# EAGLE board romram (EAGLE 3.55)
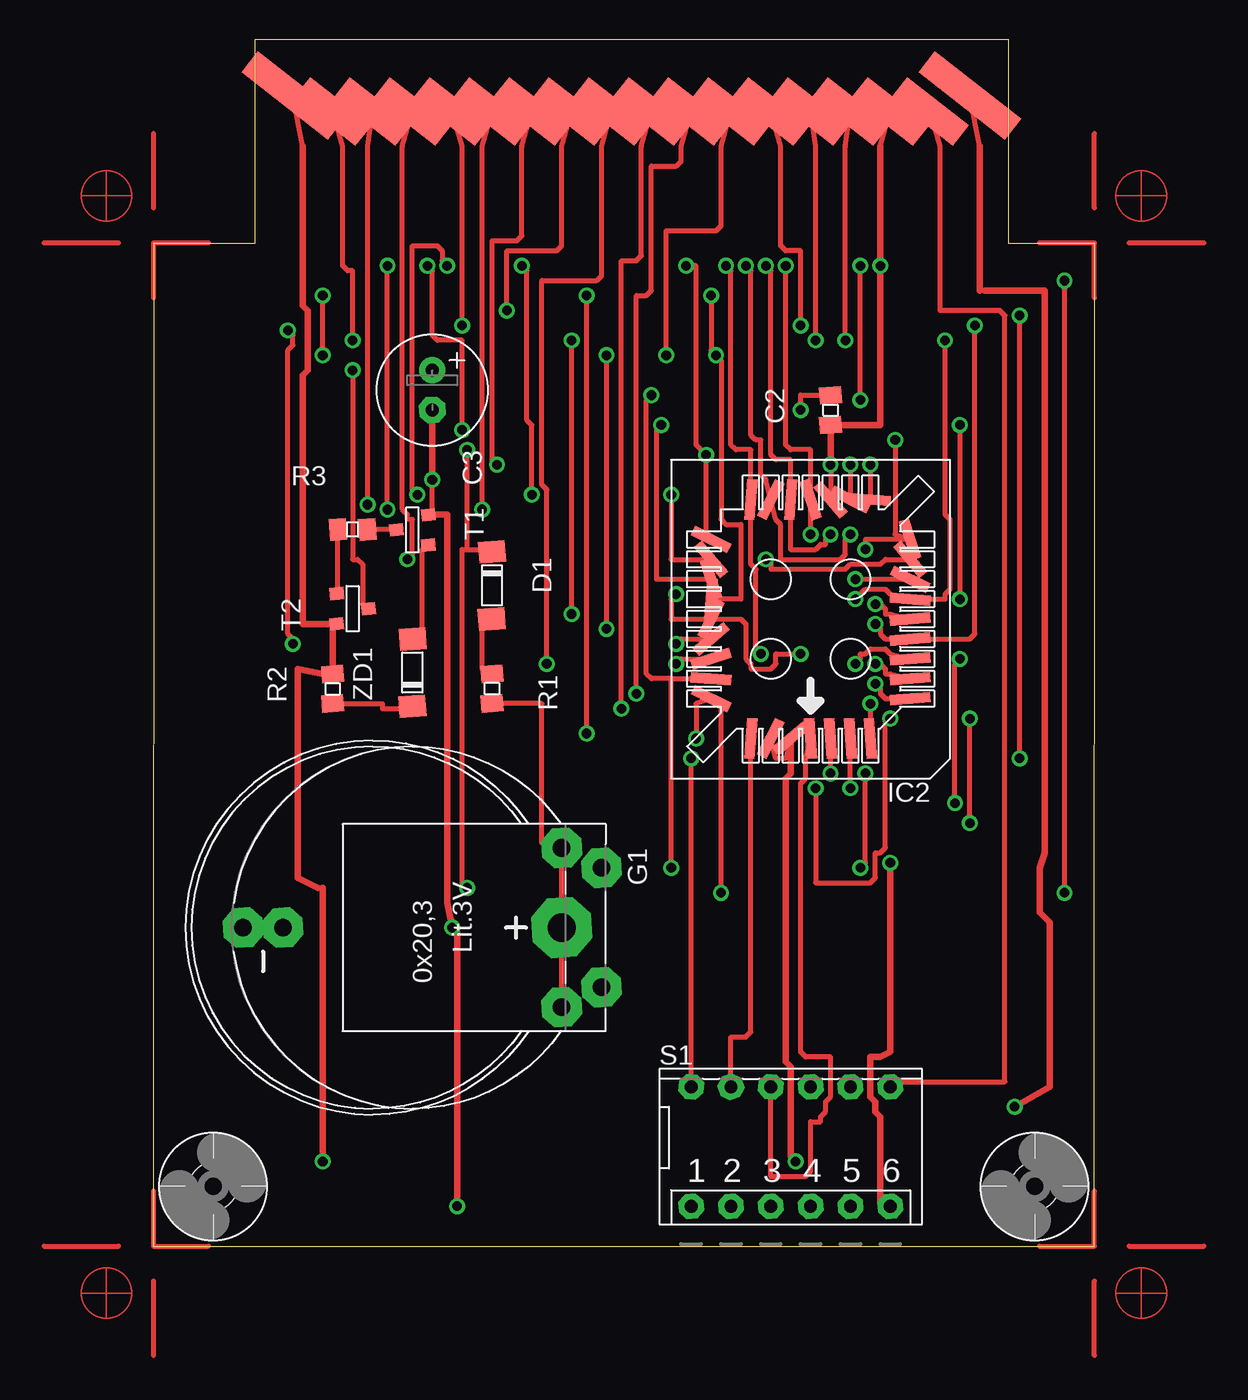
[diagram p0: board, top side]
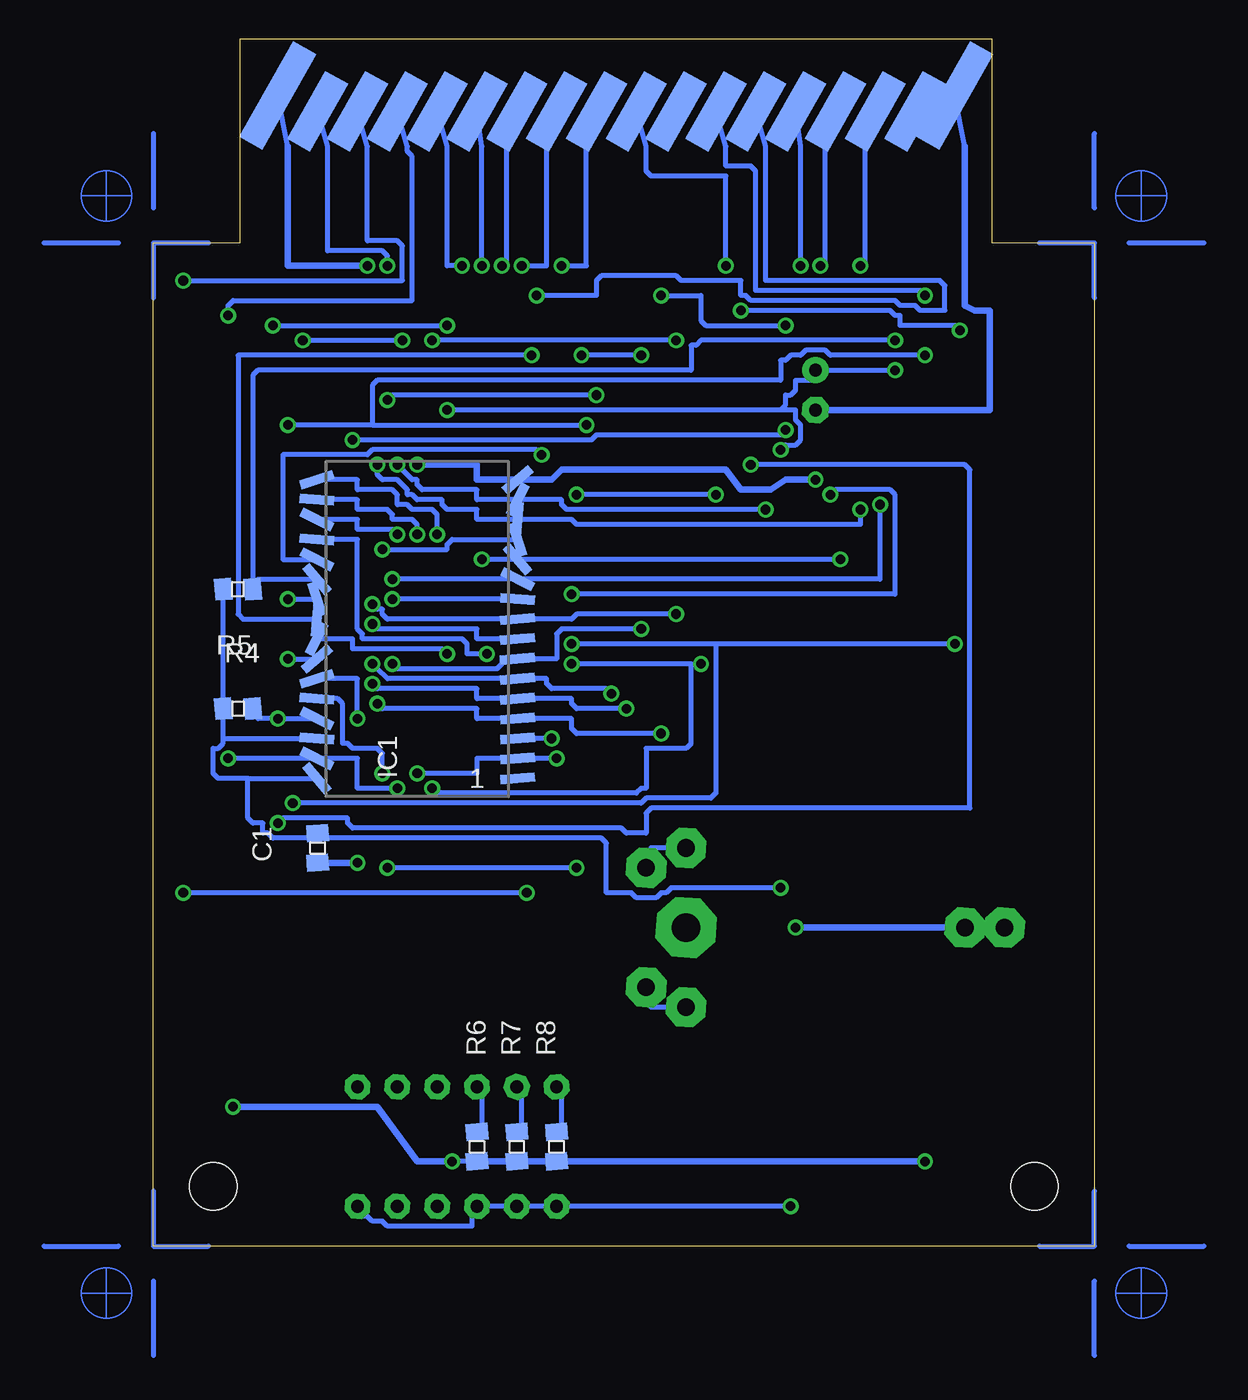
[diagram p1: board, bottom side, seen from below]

Size 60.03 x 77 mm. Coordinates in mm from the lower left corner, seen from the top.
Outline: 60.03,64.01 60.02,0 0,0 0.02,64.01
Outline: 0.01,64 6.51,64 6.51,77 54.51,77 54.51,64 60.01,64
Copper layers used: Top, Bottom
tRestrict: area 10.2,74.9 to 50.8,77.5
bRestrict: area 10.2,74.9 to 50.8,77.5
vRestrict: area 7.6,63.5 to 53.4,69.8

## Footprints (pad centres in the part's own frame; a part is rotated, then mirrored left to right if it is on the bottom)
05 = smd 1.092 x 1.397 rotated 4.4:  0.94,0 | smd 1.092 x 1.397 rotated 4.3:  -0.94,0
2,5-7 = drill 0.813 pad 1.676 round:  -1.27,0 | drill 0.813 pad 1.676 octagon:  1.27,0
KCON = smd 1.676 x 4.978 rotated 52: 0 20.32,2.54; 1 17.78,2.54; 2 15.24,2.54; 3 12.7,2.54; 4 10.16,2.54; 5 7.62,2.54; 6 5.08,2.54; 7 2.54,2.54;  22.86,2.54;  25.4,2.54;  27.94,2.54;  30.48,2.54;  33.02,2.54;  35.56,2.54;  38.1,2.54;  40.64,2.54 | smd 1.676 x 4.978 rotated 29.5 bottom: 0 20.32,2.54; 1 17.78,2.54; 2 15.24,2.54; 3 12.7,2.54; 4 10.16,2.54; 5 7.62,2.54; 6 5.08,2.54; 7 2.54,2.54;  22.86,2.54;  25.4,2.54;  27.94,2.54;  30.48,2.54;  33.02,2.54;  35.56,2.54;  38.1,2.54;  40.64,2.54 | smd 1.676 x 6.985 rotated 52: 8 0,3.556;  43.18,3.556 | smd 1.676 x 6.985 rotated 29.5 bottom: 8 0,3.556;  43.18,3.556
D-80 = smd 1.397 x 1.702 rotated 4.4:  -2.388,0 | smd 1.397 x 1.702 rotated 4.3:  1.905,-0.025
430UNI = drill 1.118 pad 2.54 octagon:  -3.81,14.605;  3.81,14.605;  0,-5.715;  5.08,12.065;  -5.08,12.065;  0,-8.255 | drill 1.803 pad 3.81 octagon:  0,12.065
P32 = smd 0.6 x 2.2 rotated 4.3:  -9.525,-6.4;  1.905,-6.4 | smd 0.6 x 2.2 rotated 4.4:  -8.255,-6.4;  5.715,6.4 | smd 0.6 x 2.2 rotated 4.5:  -6.985,-6.4;  -6.985,6.4 | smd 0.6 x 2.2 rotated 4.6:  -5.715,-6.4 | smd 0.6 x 2.2 rotated 4.7:  -4.445,-6.4;  -3.175,-6.4 | smd 0.6 x 2.2 rotated 4.8:  -1.905,-6.4 | smd 0.6 x 2.2 rotated 4.9:  -0.635,-6.4 | smd 0.6 x 2.2 rotated 5:  0.635,-6.4 | smd 0.6 x 2.2 rotated 26.8:  3.175,-6.4 | smd 0.6 x 2.2 rotated 49.3:  4.445,-6.4 | smd 0.6 x 2.2 rotated 71.8:  5.715,-6.4 | smd 0.6 x 2.2 rotated 94.3:  6.985,-6.4 | smd 0.6 x 2.2 rotated 116.8:  8.255,-6.4 | smd 0.6 x 2.2 rotated 139.3:  9.525,-6.4 | smd 0.6 x 2.2 rotated 161.8:  9.525,6.4 | smd 0.6 x 2.2 rotated 184.3:  8.255,6.4 | smd 0.6 x 2.2 rotated 206.8:  6.985,6.4 | smd 0.6 x 2.2 rotated 26.9:  4.445,6.4 | smd 0.6 x 2.2 rotated 49.4:  3.175,6.4 | smd 0.6 x 2.2 rotated 71.9:  1.905,6.4 | smd 0.6 x 2.2 rotated 94.4:  0.635,6.4 | smd 0.6 x 2.2 rotated 116.9:  -0.635,6.4 | smd 0.6 x 2.2 rotated 139.4:  -1.905,6.4 | smd 0.6 x 2.2 rotated 161.9:  -3.175,6.4 | smd 0.6 x 2.2 rotated 184.4:  -4.445,6.4 | smd 0.6 x 2.2 rotated 206.9:  -5.715,6.4 | smd 0.6 x 2.2 rotated 27:  -8.255,6.4 | smd 0.6 x 2.2 rotated 49.5:  -9.525,6.4
CC32SM = smd 2.591 x 0.66 rotated 161.9:  6.35,1.905 | smd 2.591 x 0.66 rotated 184.4:  6.35,3.175 | smd 0.66 x 2.591 rotated 4.3:  0,6.985 | smd 0.66 x 2.591 rotated 4.4:  -1.27,6.985;  3.81,-8.255 | smd 0.66 x 2.591 rotated 4.5:  -2.54,6.985;  3.81,6.985 | smd 2.591 x 0.66 rotated 139.4:  6.35,0.635 | smd 0.66 x 2.591 rotated 4.6:  -3.81,6.985 | smd 0.66 x 2.591 rotated 161.8:  0,-8.255 | smd 0.66 x 2.591 rotated 139.3:  -1.27,-8.255 | smd 0.66 x 2.591 rotated 116.8:  -2.54,-8.255 | smd 0.66 x 2.591 rotated 94.3:  -3.81,-8.255 | smd 2.591 x 0.66 rotated 71.8:  -6.35,-5.715 | smd 0.66 x 2.591 rotated 184.3:  1.27,-8.255 | smd 2.591 x 0.66 rotated 49.3:  -6.35,-4.445 | smd 2.591 x 0.66 rotated 4.7:  -6.35,4.445;  -6.35,3.175 | smd 2.591 x 0.66 rotated 4.8:  -6.35,1.905 | smd 2.591 x 0.66 rotated 4.9:  -6.35,0.635 | smd 2.591 x 0.66 rotated 5:  -6.35,-0.635 | smd 2.591 x 0.66 rotated 4.3:  -6.35,-1.905 | smd 2.591 x 0.66 rotated 26.8:  -6.35,-3.175 | smd 2.591 x 0.66 rotated 116.9:  6.35,-0.635 | smd 2.591 x 0.66 rotated 94.4:  6.35,-1.905 | smd 2.591 x 0.66 rotated 71.9:  6.35,-3.175 | smd 2.591 x 0.66 rotated 49.4:  6.35,-4.445 | smd 2.591 x 0.66 rotated 26.9:  6.35,-5.715 | smd 0.66 x 2.591 rotated 206.8:  2.54,-8.255 | smd 2.591 x 0.66 rotated 206.9:  6.35,4.445 | smd 0.66 x 2.591 rotated 27:  2.54,6.985 | smd 0.66 x 2.591 rotated 49.5:  1.27,6.985
-06 = drill 0.813 pad 1.6 octagon:  -6.35,-3.81;  -3.81,-3.81;  6.35,3.81;  3.81,3.81;  -1.27,-3.81;  1.27,-3.81;  6.35,-3.81;  3.81,-3.81;  1.27,3.81;  -1.27,3.81;  -3.81,3.81;  -6.35,3.81
T23 = smd 0.787 x 0.889 rotated 5.8:  0.991,1.016 | smd 0.787 x 0.889 rotated 6.1:  -0.94,1.016 | smd 0.787 x 0.889 rotated 5.9:  0.025,-1.016
3,0 = hole 3.023: 0,0

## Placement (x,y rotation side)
C1  100nF  [05]  49.54,25.4 90 bottom
C2  100nF  [05]  43.19,53.34 90 top
C3  47uF  [2,5-7]  17.79,54.61 270 top
CON1  TEKCON  [KCON]  8.9,69.85 0 top
D1  1N4148  [D-80]  21.6,41.91 270 top
G1  B2430UNI  [430UNI]  13.98,20.32 270 top
IC1  628128S  [P32]  43.19,39.37 90 bottom
IC2  29F040JCS  [CC32SM]  41.92,39.37 180 top
R1  200  [05]  21.6,35.56 270 top
R2  10k  [05]  11.44,35.56 90 top
R3  510  [05]  12.71,45.72 180 top
R4  1k  [05]  54.62,34.29 0 bottom
R5  1k  [05]  54.62,41.91 180 bottom
R6  10k  [05]  39.38,6.35 90 bottom
R7  10k  [05]  36.84,6.35 90 bottom
R8  10k  [05]  34.3,6.35 90 bottom
S1  DP06  [-06]  40.65,6.35 0 top
T1  BC848  [T23]  16.52,45.72 270 top
T2  BC858  [T23]  12.71,40.64 90 top
U$1  [H]  0.01,64 180 top
U$2  [H]  60.01,64 90 top
U$3  [H]  0.01,0 270 top
U$4  [H]  60.01,0 0 top
U$5  [IZ]  -2.99,67 0 top
U$6  [IZ]  63.01,67 0 top
U$7  [IZ]  63.01,-3 0 top
U$8  [IZ]  -2.99,-3 0 top
U$9  [3,0]  56.21,3.81 0 top
U$10  [3,0]  3.82,3.81 0 top
ZD1  3.6V  [D-80]  16.52,36.83 90 top

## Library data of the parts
C1 C2 D1 R1-R8 ZD1 = SMD
C3 = cap-pan
CON1 IC2 = Moje1
G1 = BATTERY
IC1 = MEMHITCH
S1 = DILSWTCH
T1 T2 = TRANS-SM
U$1-U$8 = VYKRESY
U$9 U$10 = HOLES

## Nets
+5V: CON1. CON1.8 IC2. R2. R6. R7. R8. T2.
A0: CON1.5 IC1. IC2.
A1: CON1.6 IC1. IC2.
A2: CON1. IC1. IC2.
A3: CON1. IC1. IC2.
A4: CON1. IC1. IC2.
A5: CON1. IC1. IC2.
A6: CON1. IC1. IC2.
A7: CON1. IC1. IC2.
A8: CON1.0 IC1. IC2.
A9: CON1.1 IC1. IC2.
A10: CON1.2 IC1. IC2.
A11: CON1.4 IC1. IC2.
A12: CON1.4 IC1. IC2.
A13: CON1. IC1. IC2.
A14: CON1. IC1. IC2.
A15: CON1. IC1. IC2.
A16: IC1. IC2. R8. S1.
A17: IC2. R7. S1.
A18: IC2. R6. S1.
D0: CON1.5 IC1. IC2.
D1: CON1.6 IC1. IC2.
D2: CON1.3 IC1. IC2.
D3: CON1. IC1. IC2.
D4: CON1. IC1. IC2.
D5: CON1. IC1. IC2.
D6: CON1. IC1. IC2.
D7: CON1. IC1. IC2.
GND: C1. C2. C3. CON1. CON1.8 G1. IC1. IC2. S1. T1.
N$1: CON1.3 IC1. IC2.
N$2: R3. T2.
N$3: G1. R1.
N$4: D1. R1.
N$5: R3. T1.
N$6: R2. ZD1.
N$7: T1. ZD1.
N$9: CON1. S1.
N$10: CON1.0 IC2.
N$11: CON1.7 IC1. R5.
N$22: CON1.2 IC1. R4.
VBAT: C1. C2. C3. D1. IC1. R4. R5. T2.

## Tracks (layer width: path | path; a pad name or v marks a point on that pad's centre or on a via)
+5V  (via drill 0.61 pad 1.02)
  Top 0.305: 11.44,39.37 11.69,39.7 11.44,39.69 | 9.54,70.17 CON1.8 | 39.38,32.38 39.7,31.11 40.33,31.11 40.65,32.38 | v40.97,5.4 40.65,5.71 | 53.03,60.96 52.71,60.96 | 52.71,70.17 52.08,73.41 | 10.8,22.86 10.49,22.86 | 10.8,36.51 11.44,36.5
  Top 0.406: 11.44,36.5 11.44,39.37 | 11.44,39.69 9.54,39.69 9.54,55.56 9.85,55.88 9.85,59.69 9.54,60.01 9.54,70.17 | 40.65,5.71 40.65,11.43 40.33,11.75 40.33,29.84 40.65,30.16 40.65,32.38 | 52.71,60.96 52.71,70.17 | 53.03,60.96 56.84,60.96 56.84,25.08 56.52,24.13 56.52,21.27 57.16,20.64 57.16,10.16 v54.94,8.89 | 10.8,36.51 9.22,36.83 9.22,23.5 10.49,22.86 | v10.8,5.4 10.8,22.86
  Bottom 0.305: 34.93,5.4 R8. 33.66,5.4 | 36.2,5.4 R7. 37.48,5.4 | 38.74,5.4 R6. 40.02,5.4 v40.97,5.4
  Bottom 0.406: 34.93,5.4 36.2,5.4 | 37.48,5.4 38.74,5.4 | v40.97,5.4 43.19,5.4 45.73,8.89 v54.94,8.89 | v10.8,5.4 33.66,5.4
A0  (via drill 0.61 pad 1.02)
  Top 0.305: v39.06,43.81 39.38,43.5 39.38,43.18 44.14,43.18 44.46,43.5 46.36,43.5 46.68,43.81 48.27,43.81 | v16.2,43.81 16.52,44.13 16.52,46.35 16.2,46.35 16.2,46.67 15.88,46.99 15.88,70.17 CON1.5
  Bottom 0.305: v39.06,43.81 36.79,43.81 v16.2,43.81
A1  (via drill 0.61 pad 1.02)
  Top 0.305: v44.78,42.55 48.27,42.55 | v13.66,47.31 13.66,70.17 CON1.6
  Bottom 0.305: v44.78,42.55 36.79,42.55 13.66,42.55 v13.66,47.31
A2  (via drill 0.61 pad 1.02)
  Top 0.305: v44.78,41.27 45.09,41.27 45.09,41.59 45.41,41.91 46.68,41.91 47,41.59 48.27,41.27 50.49,41.27 50.49,41.59 50.81,41.91 50.81,46.35 50.49,46.67 v50.49,57.78 | v44.14,57.78 44.14,70.17 44.46,72.39
  Bottom 0.305: 36.79,41.27 v44.78,41.27 | v50.49,57.78 v44.14,57.78
A3  (via drill 0.61 pad 1.02)
  Top 0.305: v46.05,40.96 46.36,40.96 46.68,40.64 46.68,40.32 47,40.32 48.27,40.01 | v42.24,57.78 42.24,70.17 41.92,72.39 | v26.68,40.32 v26.68,57.78
  Bottom 0.305: v46.05,40.96 45.73,40.64 45.41,40.64 45.41,40.32 45.09,40.01 36.79,40.01 33.35,40.01 33.03,40.32 v26.68,40.32 | v26.68,57.78 v42.24,57.78
A4  (via drill 0.61 pad 1.02)
  Top 0.305: v46.05,39.69 46.36,39.37 46.36,39.05 46.68,38.73 48.27,38.73 52.08,38.73 52.4,39.05 v52.4,58.74 | v41.28,58.74 41.28,63.5 40.33,63.5 40.02,63.82 40.02,70.17 39.38,72.39
  Bottom 0.305: v46.05,39.69 45.73,39.37 39.38,39.37 39.38,38.73 36.79,38.73 | v52.4,58.74 v41.28,58.74
A5  (via drill 0.61 pad 1.02)
  Top 0.305: v44.78,37.15 45.09,37.47 45.09,37.78 45.41,37.78 45.73,38.1 46.68,38.1 47,37.78 48.27,37.47 | v32.71,56.83 32.71,64.77 35.89,64.77 36.2,65.09 36.2,70.17 36.84,72.39 | v28.9,39.37 v28.9,56.83
  Bottom 0.305: v44.78,37.15 44.46,36.83 38.11,36.83 37.79,37.15 37.79,37.47 36.79,37.47 34.3,37.47 34.3,39.05 33.98,39.37 v28.9,39.37 | v28.9,56.83 v32.71,56.83
A6  (via drill 0.61 pad 1.02)
  Top 0.305: v46.05,37.15 46.36,37.15 46.68,36.83 46.68,36.51 47,36.51 48.27,36.2 | v30.81,35.24 30.81,60.64 31.44,60.64 31.76,60.96 31.76,68.9 33.35,68.9 33.66,69.22 33.66,70.17 34.3,72.39
  Bottom 0.305: v46.05,37.15 46.05,36.83 45.73,36.83 45.09,36.2 36.79,36.2 34.93,36.2 34.93,35.88 34.62,35.56 31.12,35.56 v30.81,35.24
A7  (via drill 0.61 pad 1.02)
  Top 0.305: v46.05,35.88 46.36,35.56 46.36,35.24 46.68,34.92 48.27,34.92 | v29.86,34.29 29.86,62.87 30.81,62.87 31.12,63.18 31.12,70.17 31.76,72.39
  Bottom 0.305: v46.05,35.88 45.73,35.56 39.38,35.56 39.38,34.92 36.79,34.92 33.35,34.92 33.35,34.61 33.03,34.29 v29.86,34.29
A8  (via drill 0.61 pad 1.02)
  Top 0.305: v47,33.66 46.68,33.34 46.68,25.4 46.36,25.08 46.05,25.08 46.05,23.5 45.73,23.18 42.24,23.18 v42.24,29.21 | v33.35,37.15 33.66,37.47 35.57,37.47 | v25.09,37.15 25.09,48.26 24.78,48.58 24.78,61.59 28.27,61.59 28.59,61.91 28.59,70.17 CON1.0
  Bottom 0.305: v47,33.66 47,36.2 49.59,36.2 | v42.24,29.21 41.92,28.89 29.22,28.89 28.9,29.21 28.59,29.21 28.59,31.75 26.05,31.75 25.73,32.07 25.73,37.15 | 25.73,37.15 v33.35,37.15 | 25.73,37.15 v25.09,37.15
A9  (via drill 0.61 pad 1.02)
  Top 0.305: v51.45,37.47 51.13,37.15 v51.13,28.26 | v33.35,38.42 33.66,38.73 35.57,38.73 | v22.55,59.69 22.55,63.5 25.73,63.5 26.05,63.82 26.05,70.17 CON1.1 | v8.58,58.42 8.9,58.1 8.9,57.47 8.58,57.15 8.58,39.05 8.9,38.73 v8.9,38.42
  Bottom 0.305: v51.13,28.26 28.9,28.26 28.59,28.57 24.46,28.57 24.14,28.89 24.14,38.42 | 24.14,38.42 v33.35,38.42 | v51.45,37.47 49.59,37.47 | v22.55,59.69 13.03,59.69 12.71,59.37 12.39,59.37 12.39,58.74 8.9,58.74 v8.58,58.42 | v8.9,38.42 24.14,38.42
A10  (via drill 0.61 pad 1.02)
  Top 0.305: v51.45,52.39 v51.45,41.27 | v32.39,52.39 32.08,52.07 32.08,42.55 35.57,42.55 | v10.8,56.83 v10.8,60.64
  Bottom 0.305: 46.05,52.39 v32.39,52.39 | 46.05,52.39 v51.45,52.39 | v51.45,41.27 49.59,41.27 | v10.8,60.64 11.12,60.96 21.6,60.96 21.6,68.58 21.92,68.9 23.51,68.9 23.51,70.17 CON1.2 | v10.8,56.83 16.84,56.83 17.16,57.15 18.43,57.15 18.74,56.83 19.38,56.83 19.7,56.52 20.01,56.52 20.01,55.24 45.73,55.24 46.05,54.93 46.05,52.39
A11  (via drill 0.61 pad 1.02)
  Top 0.305: v41.28,37.78 39.7,37.78 39.7,37.15 39.38,36.83 38.11,36.83 38.11,37.15 37.79,37.47 37.79,39.69 37.48,40.01 35.57,40.01 33.03,40.01 33.03,41.27 v33.35,41.59 | v18.74,62.55 18.43,62.87 18.43,63.5 18.11,63.82 16.52,63.82 16.52,48.26 v16.84,47.94
  Bottom 0.305: v41.28,37.78 41.6,38.1 47.32,38.1 47.32,38.73 49.59,38.73 | v18.74,62.55 18.74,70.17 CON1.4 | v16.84,47.94 16.52,48.26 13.03,48.26 12.71,47.94 12.71,41.59 v33.35,41.59
A12  (via drill 0.61 pad 1.02)
  Top 0.305: v45.73,34.61 45.73,32.38 | v19.7,58.74 19.7,70.17 CON1.4 | v27.63,32.7 v27.63,60.64
  Bottom 0.305: v45.73,34.61 45.41,34.29 39.38,34.29 39.38,33.66 36.79,33.66 33.35,33.66 33.35,33.02 33.03,32.7 v27.63,32.7 | v19.7,58.74 24.78,58.74 25.09,59.05 25.09,60.64 v27.63,60.64
A13  (via drill 0.61 pad 1.02)
  Top 0.305: v45.41,30.16 45.41,24.45 v45.09,24.13 | v33.03,24.13 33.03,36.2 | 33.03,36.2 35.57,36.2 | v45.09,53.98 v45.09,62.55 | v31.76,54.29 31.44,53.98 31.44,36.51 31.76,36.2 33.03,36.2
  Bottom 0.305: v45.41,30.16 45.41,31.43 45.73,31.75 47.32,31.75 47.63,32.07 47.95,32.07 47.95,34.61 48.27,34.92 49.59,34.92 | v33.03,24.13 v45.09,24.13 | v45.09,62.55 45.09,63.18 45.41,63.5 48.91,63.5 48.91,70.17 CON1. | v45.09,53.98 44.78,54.29 v31.76,54.29
A14  (via drill 0.61 pad 1.02)
  Top 0.305: v34.62,32.38 34.62,34.61 35.57,34.92 36.2,34.61 v36.2,22.54 | v58.11,22.54 v58.11,61.59
  Bottom 0.305: v34.62,32.38 36.79,32.38 | v58.11,61.59 44.14,61.59 44.14,63.82 44.46,64.14 46.36,64.14 46.36,70.17 47,72.39 | v36.2,22.54 v58.11,22.54
A15  (via drill 0.61 pad 1.02)
  Top 0.305: v44.46,29.21 44.46,32.38 | v55.25,31.11 v55.25,59.37
  Bottom 0.305: v44.46,29.21 47,29.21 47,31.11 49.59,31.11 v55.25,31.11 | v55.25,59.37 55.25,60.01 54.94,60.33 43.51,60.33 43.51,69.53 43.82,69.85 43.82,70.17 44.46,72.39
A16  (via drill 0.61 pad 1.02)
  Top 0.305: v43.19,30.16 43.19,32.38 | S1. v34.3,31.11
  Bottom 0.305: 34.3,7.29 33.98,7.62 33.98,9.53 S1. | v43.19,30.16 39.38,30.16 39.38,31.11 36.79,31.11 v34.3,31.11
A17
  Top 0.305: IC2. 38.11,13.65 37.79,13.34 36.84,13.34 36.84,10.16
  Bottom 0.305: 36.84,7.29 36.52,7.62 36.52,9.53 36.84,10.16
A18
  Top 0.305: 41.92,32.38 41.6,31.11 41.6,29.84 41.28,29.53 41.28,12.38 41.6,12.06 43.19,12.06 43.19,9.53 42.87,9.21 42.87,8.57 42.55,8.26 42.55,7.94 41.92,7.94 41.92,4.76 41.6,4.45 39.38,4.45 39.38,10.16
  Bottom 0.305: 39.38,7.29 39.06,7.62 39.06,9.53 39.38,10.16
D0  (via drill 0.61 pad 1.02)
  Top 0.305: v45.41,44.45 45.41,45.09 48.27,45.09 47.32,45.4 v47.32,51.44 | v17.47,62.55 17.79,62.23 17.79,58.1 18.11,57.78 19.7,57.78 v19.7,52.07
  Bottom 0.305: v45.41,44.45 41.28,44.45 41.28,44.77 40.97,45.09 36.79,45.09 | v17.47,62.55 17.16,62.55 17.16,70.17 CON1.5 | v19.7,52.07 20.01,51.75 31.76,51.75 32.08,51.44 v47.32,51.44
D1  (via drill 0.61 pad 1.02)
  Top 0.305: v45.73,49.85 45.73,47.62 | v14.93,46.99 v14.93,62.55
  Bottom 0.305: v45.73,49.85 45.73,49.21 45.41,48.9 44.46,48.9 43.82,48.26 43.82,47.94 43.51,47.94 43.19,47.62 41.6,47.62 41.6,47.31 41.28,46.99 39.38,46.99 39.38,46.35 36.79,46.35 33.35,46.35 33.03,46.04 14.93,46.04 v14.93,46.99 | v14.93,62.55 14.62,62.55 14.62,70.17 CON1.6
D2  (via drill 0.61 pad 1.02)
  Top 0.305: v44.46,49.85 44.46,47.62 | v20.96,46.99 20.96,70.17 CON1.3
  Bottom 0.305: v44.46,49.85 44.46,49.53 44.14,49.53 43.51,48.9 43.19,48.9 43.19,48.58 42.87,48.26 39.38,48.26 39.38,47.62 36.79,47.62 33.98,47.62 33.98,47.31 33.66,46.99 v20.96,46.99
D3  (via drill 0.61 pad 1.02)
  Top 0.305: v41.92,45.4 41.92,47.62 41.92,50.8 40.65,50.8 40.33,51.12 v40.33,62.55
  Bottom 0.305: v41.92,45.4 41.92,46.67 42.24,46.99 43.51,46.99 43.82,47.31 44.46,47.31 44.46,47.94 44.78,48.26 47,48.26 47,48.9 49.59,48.9 | v40.33,62.55 41.28,62.55 41.28,70.17 41.92,72.39
D4  (via drill 0.61 pad 1.02)
  Top 0.305: v43.19,45.4 42.87,45.09 42.87,44.77 42.55,44.77 42.24,44.45 40.65,44.45 40.65,47.62 40.65,50.16 39.7,50.16 39.38,50.48 39.38,62.23 v39.06,62.55
  Bottom 0.305: v43.19,45.4 43.19,46.04 43.51,46.35 44.78,46.35 44.78,46.67 45.09,46.99 47,46.99 47,47.62 49.59,47.62 | v39.06,62.55 39.06,70.17 39.38,72.39
D5  (via drill 0.61 pad 1.02)
  Top 0.305: v44.46,45.4 44.14,45.09 44.14,44.13 43.82,43.81 40.02,43.81 40.02,46.04 39.7,46.35 39.38,47.62 39.06,48.9 38.74,49.21 38.74,51.44 38.43,51.44 38.11,51.75 38.11,62.23 v37.79,62.55
  Bottom 0.305: v44.46,45.4 44.78,45.72 47,45.72 47,46.35 49.59,46.35 | v37.79,62.55 37.48,62.55 37.48,70.17 36.84,72.39
D6  (via drill 0.61 pad 1.02)
  Top 0.305: v38.74,37.78 38.43,38.1 38.43,43.18 38.11,43.5 38.11,47.62 38.11,50.8 37.16,50.8 36.84,51.12 36.84,62.23 v36.52,62.55
  Bottom 0.305: v38.74,37.78 40.02,37.78 40.02,38.42 40.33,38.73 46.68,38.73 46.68,39.05 47,39.37 47,45.09 49.59,45.09 | v36.52,62.55 34.93,62.55 34.93,70.17 34.3,72.39
D7  (via drill 0.61 pad 1.02)
  Top 0.305: 35.57,45.09 35.25,45.4 v35.25,50.48 34.62,51.12 34.62,62.55 v33.98,62.55
  Bottom 0.305: v35.25,50.48 35.57,50.8 46.05,50.8 46.36,50.48 51.76,50.48 51.76,43.81 49.59,43.81 | v33.98,62.55 32.39,62.55 32.39,70.17 31.76,72.39
GND  (via drill 0.61 pad 1.02)
  Top 0.305: v43.19,49.85 43.19,47.62 | 46.36,70.17 47,72.39 | C2. 43.82,52.39 | 47,24.13 v47,24.45 | 47,2.54 46.36,2.86 | v17.79,48.9 17.79,46.99 17.54,46.66 17.47,46.67 | 19.38,20 v19.06,20.32
  Top 0.406: v43.19,49.85 C2. | 46.36,70.17 v46.36,62.55 46.36,52.39 43.82,52.39 | 47,24.13 47,12.38 46.36,12.06 45.73,12.06 45.73,9.53 46.05,9.21 46.05,8.57 46.36,8.26 46.36,2.86 | v17.79,48.9 C3. | v19.06,20.32 18.74,21.91 18.74,46.67 17.47,46.67 | v19.38,2.54 19.38,20
  Bottom 0.305: 51.45,70.17 52.08,73.41 | 48.91,24.45 C1. | 47,2.54 46.68,1.91 46.36,1.91 46.05,1.59 45.41,1.59 45.09,1.27 39.7,1.27 39.7,1.91 39.38,2.54 36.84,2.54 34.3,2.54 v19.38,2.54 | 8.27,70.17 CON1.8
  Bottom 0.406: v43.19,49.85 39.38,49.85 39.38,48.9 36.79,48.9 34.62,48.9 33.98,49.53 23.51,49.53 22.55,48.26 20.65,48.26 19.7,48.9 v17.79,48.9 | 51.45,70.17 51.45,62.55 v46.36,62.55 | v47,24.45 48.91,24.45 | v19.06,20.32 8.27,20.32 | 8.27,70.17 8.27,60.01 7.63,59.69 6.68,59.69 6.68,53.34 C3.
N$1  (via drill 0.61 pad 1.02)
  Top 0.305: 35.57,41.27 37.48,41.27 37.48,46.04 36.52,46.04 36.2,46.35 36.2,56.52 v35.89,56.83 35.57,57.15 v35.57,60.64
  Bottom 0.305: v35.89,56.83 54.62,56.83 54.62,40.32 54.3,40.01 49.59,40.01 | v35.57,60.64 31.76,60.64 31.76,61.59 31.44,61.91 26.68,61.91 26.36,61.59 22.55,61.59 22.55,60.64 22.24,60.64 21.92,60.33 12.71,60.33 12.39,60.01 11.44,60.01 11.12,59.69 9.54,59.69 9.54,61.28 9.85,61.59 20.96,61.59 20.96,70.17 CON1.3
N$2
  Top 0.305: 11.69,41.63 11.76,41.91 11.76,45.09 11.77,45.72
N$3
  Top 0.305: 26.05,15.24 G1. 26.05,25.4 24.78,25.72 24.78,34.61 22.24,34.61 21.6,34.62
  Bottom 0.305: 28.59,16.51 28.27,15.24 26.05,15.24 | 28.59,24.13 28.27,25.4 26.05,25.4
N$4
  Top 0.305: R1. 20.96,36.83 20.96,39.37 D1.
N$5
  Top 0.305: T1. 15.25,45.72 R3.
N$6
  Top 0.305: R2. 12.07,34.61 14.62,34.61 14.62,34.29 15.88,34.29 16.52,34.44
N$7
  Top 0.305: 17.54,44.73 17.16,44.45 17.16,39.37 ZD1.
N$9
  Top 0.305: 47,10.16 47.63,10.48 54.3,10.48 54.3,59.37 53.98,59.69 50.17,59.69 50.17,70.17 CON1.
N$10  (via drill 0.61 pad 1.02)
  Top 0.305: v33.03,47.94 33.03,43.81 35.57,43.81 | v24.14,47.94 24.14,52.39 23.82,52.7 23.82,62.23 v23.51,62.55
  Bottom 0.305: v24.14,47.94 v33.03,47.94 | v23.51,62.55 23.51,68.26 28.27,68.26 28.59,68.58 28.59,70.17 CON1.0
N$11  (via drill 0.61 pad 1.02)
  Top 0.305: v12.71,57.78 12.71,62.23 12.39,62.23 12.07,62.55 12.07,70.17 CON1.7
  Bottom 0.305: 49.59,42.55 53.35,42.55 R5. 53.67,42.55 53.67,55.56 53.35,55.88 25.73,55.88 25.73,57.47 25.41,57.47 25.09,57.78 v12.71,57.78
N$22  (via drill 0.61 pad 1.02)
  Top 0.305: v21.92,49.85 21.6,50.16 21.6,64.14 23.19,64.14 23.51,64.45 23.51,70.17 CON1.2 | v52.08,26.99 v52.08,33.66
  Bottom 0.305: 53.68,34.29 53.35,33.66 v52.08,33.66 49.59,33.66 | v21.92,49.85 8.27,49.85 7.95,49.53 7.95,27.94 28.27,27.94 28.59,27.62 28.59,26.35 29.86,26.35 30.17,26.67 47.32,26.67 47.63,26.99 47.63,27.3 51.76,27.3 v52.08,26.99
VBAT  (via drill 0.61 pad 1.02)
  Top 0.305: v12.71,55.88 12.71,43.81 13.03,43.81 13.35,43.5 13.35,40.96 T2. | v41.28,53.34 41.28,54.29 42.55,54.29 43.19,54.28 | 20.01,44.45 20.96,44.45 21.6,44.3 | 20.01,44.45 v20.01,50.8 | v20.01,22.86 19.7,23.18 19.7,44.45 20.01,44.45
  Bottom 0.305: 53.98,29.84 53.98,27.3 53.67,26.99 53.03,26.99 53.03,26.35 52.71,26.35 52.4,26.04 50.17,26.04 49.54,26.34 48.91,26.04 31.44,26.04 31.12,25.72 31.12,22.54 29.54,22.54 29.22,22.23 27.95,22.23 27.63,22.54 27.32,22.54 27,22.86 v20.01,22.86 | 53.98,29.84 IC1. | 55.57,32.38 55.57,33.66 R4. 55.57,34.92 55.57,41.27 55.56,41.91 | 55.57,32.38 49.59,32.38 | 53.98,29.84 55.89,29.84 56.21,30.16 56.21,31.75 55.89,31.75 55.57,32.07 55.57,32.38 | v12.71,55.88 17.79,55.88 18.11,55.24 19.06,55.24 19.06,54.61 19.38,54.29 19.7,54.29 19.7,53.66 20.01,53.34 | 20.01,53.34 v41.28,53.34 | v20.01,50.8 19.7,51.12 19.06,51.12 18.74,51.44 18.74,52.39 19.06,52.7 19.06,53.34 20.01,53.34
